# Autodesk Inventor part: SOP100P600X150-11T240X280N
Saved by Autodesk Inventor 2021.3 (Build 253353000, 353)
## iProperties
Created: 2021-12
Part Number: SOP100P600X150-11T240X280N
Material: Generic
Document SubType Name: Modeling
Designer: Administrator
Density: 1 g/cm^3
Appearance: Default
Title: SOP100P600X150-11T240X280N
Author: Administrator
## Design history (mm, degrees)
feature "Body1"
body "Solid1"
